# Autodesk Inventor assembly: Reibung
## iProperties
Created: 2009-12
Part Number: Reibung
Document SubType Name: Assembly
Designer: AEW
Mass: 6962.5 g
Surface Area: 610 cm^2
Volume: 262.5 cm^3
Density: 26.5238 g/cm^3
Author: AEW
